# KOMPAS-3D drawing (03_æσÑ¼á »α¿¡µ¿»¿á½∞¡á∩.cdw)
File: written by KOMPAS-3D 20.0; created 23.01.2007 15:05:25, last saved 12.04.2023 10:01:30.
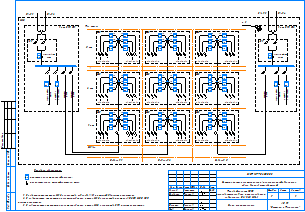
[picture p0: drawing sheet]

Sheet 1: A3, landscape

Document properties: Автор: Лескин; Организация: ЗАО ИТФ "СИСТЕМЫ И ТЕХНОЛОГИИ"; Разработал: Антошин; Проверил: Тарасов; Утвердил: Шмончев; Н. контр.: Силаков; Полное имя файла: \\s-tech\depts\Отдел_ПКО\Проекты\Типовые проекты МКД 2023\!Типовой проект\2_Типовой проект МКД_Радиоканал\03_Схема принципиальная.cdw

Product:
- Part/product: (unnamed)
  - Component: \\Helios\отдел_пко\Общая папка Компас\_Addons\Signatures\Signatures.lfr|Шмончев  | Полное имя файла: C:\Users\MAntoshin\AppData\Local\Temp\hsklda.frw; source file: C:\Program Files\ASCON\KOMPAS-3D V13\Libs\_Addons\Signatures\Signatures.lfr
  - Component: \\Helios\отдел_пко\Общая папка Компас\_Addons\Signatures\Signatures.lfr|Силаков  | Полное имя файла: C:\Users\MAntoshin\AppData\Local\Temp\eiczbt.frw; source file: C:\Program Files\ASCON\KOMPAS-3D V13\Libs\_Addons\Signatures\Signatures.lfr
  - Component: \\Helios\отдел_пко\Общая папка Компас\_Addons\Signatures\Signatures.lfr|Тарасов  | Полное имя файла: C:\Users\MAntoshin\AppData\Local\Temp\qlkzkl.frw; source file: C:\Program Files\ASCON\KOMPAS-3D V13\Libs\_Addons\Signatures\Signatures.lfr

Title block, sheet 1: designation: ВЛСТ 1277.02.000 СЭ; Количество листов документа: 1; organisation: АО ГК / "Системы и Технологии"; Форматы листов документа: A3; stored path: C:\Program Files\ASCON\KOMPAS-3D V8 Plus\Templates\Чертеж строительный зданий и сооружений.cdt; cell 302: Система учета электроэнергии (с организацией удаленного / сбора данных) потребителей; cell 303: Типовой проект ИСУЭ / многоквартирного дома с использованием / радиоканала (F2/868 МГц); cell 304: Схема принципиальная; cell 320: Р

Referenced files in \\Helios\отдел_пко\Общая папка Компас\_Addons\Signatures\: Signatures.lfr|Тарасов, Signatures.lfr, Signatures.lfr|Силаков, Signatures.lfr|Шмончев
Referenced files in C:\Program Files\ASCON\KOMPAS-3D V13\Libs\_Addons\Signatures\: Signatures.lfr
Referenced files: qlkzkl.frw, eiczbt.frw, hsklda.frw
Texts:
  Тарасов
  Силаков
  Шмончев
  Normal
  Body Text,Письмо в Интернет,body text
  TXT
  Centerline
  Outline
  АВР
  Ввод 1
  Ввод 2
  Общедомовой
  учет
  Лифтовое
  оборудование
  Этажные
  щиты
  Общедомойвые
  нужды
  МКД
  Кв.1
  Кв.2
  Тех. этаж
  Подъезд 1
  Подвал
  Подъезд 2
  Ввод 3
  Ввод 4
  Общедомойвой
  Подъезд N
  Кв.3
  Кв.4
  Кв.5
  Кв.6
  - счетчик электрической энергии;
  - измерительные трансформаторы тока.
  может изменяться.
  N эт
  POLYLINE_STYLE_0.09_RGB_0_0_0
  POLYLINE_STYLE_0.18_RGB_0_0_0
  POLYLINE_STYLE_0.09_RGB_0_0_255
  Черная основная
  Красная штриховая
  сплошная своя 0,54 мм на бумаге
  Красная основная
  CONTINUOUS0
  POLYLINE_STYLE_0.18_RGB_255_0_0
  CONTINUOUS_RGB_0_0_0_THICK_0.25
  Стили документа
  Разраб.
  Н.контр.
  Утв.
  Антошин
  03 Рабочие чертежи основного комплекта. ГОСТ 21.101-97 Ф3
Dimensions and other numbers on the sheet: 1,8; 2,5; 1 эт, ВРУ №1; 1 эт; 2 эт; 1 эт, ВРУ №2; 04.23; 1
